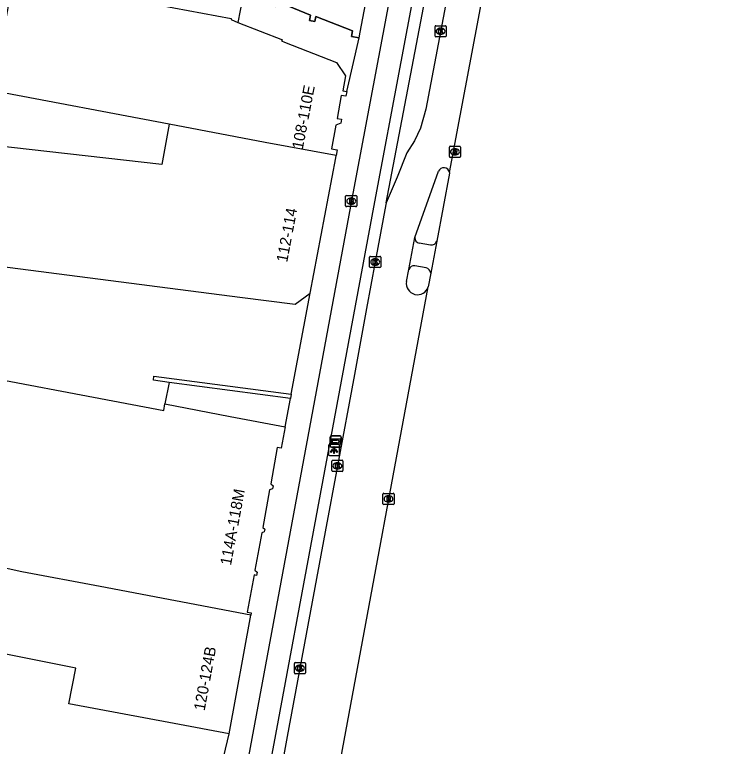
# Model space of a CAD drawing. Extents: x 161402 to 161933, y 381650 to 382313.
# Drawn here: x 161827.2 to 161890, y 381730.8 to 381796.3 of the extents above; entities that cross this region are included whole.
import ezdxf

# ---------------------------------------------------------------- set-up
doc = ezdxf.new("R2010")
doc.units = 0
for name, color, linetype in [('IMGEO_Brandkraan', 7, 'Continuous'), ('IMGEO_Fietspad_gesloten', 7, 'Continuous'), ('IMGEO_Kolk', 7, 'Continuous'), ('IMGEO_Lichtpunt', 7, 'Continuous'), ('IMGEO_OVBaan_gesloten', 7, 'Continuous'), ('IMGEO_Pand', 7, 'Continuous'), ('IMGEO_Pand_nummerreeks', 7, 'Continuous'), ('IMGEO_Pand_overbouw', 7, 'Continuous'), ('IMGEO_Parkeervlak_open', 7, 'Continuous'), ('IMGEO_Rijbaan_lokaal_gesloten', 7, 'Continuous'), ('IMGEO_Rioolput', 7, 'Continuous'), ('IMGEO_Voetpad_open', 7, 'Continuous'), ('IMGEO_Wegwijzer', 7, 'Continuous')]:
    doc.layers.add(name, color=color, linetype=linetype)

msp = doc.modelspace()

# ---------------------------------------------------------------- linework, layer by layer
at = {"layer": 'IMGEO_Brandkraan'}
for p, q in [((161856.902, 381779.209), (161856.902, 381780.061)), ((161856.977, 381780.135), (161857.829, 381780.135)), ((161857.903, 381780.061), (161857.903, 381779.209)), ((161857.413, 381779.355), (161857.388, 381779.355)), ((161857.39, 381779.915), (161857.415, 381779.915)), ((161857.829, 381779.135), (161856.977, 381779.135))]:
    msp.add_line(p, q, dxfattribs=at)
for points in [[(161856.902, 381779.209), (161856.902, 381780.061)], [(161856.977, 381780.135), (161857.829, 381780.135)], [(161857.903, 381780.061), (161857.903, 381779.209)], [(161857.25, 381779.835), (161857.25, 381779.435), (161857.463, 381779.435)], [(161857.481, 381779.835), (161857.25, 381779.835)], [(161857.429, 381779.754), (161857.375, 381779.754), (161857.375, 381779.678)], [(161857.375, 381779.678), (161857.428, 381779.678)], [(161857.437, 381779.602), (161857.375, 381779.602), (161857.375, 381779.521)], [(161857.375, 381779.521), (161857.437, 381779.521)], [(161857.829, 381779.135), (161856.977, 381779.135)]]:
    msp.add_lwpolyline(points, dxfattribs=at)
for centre, radius, start, end in [((161856.979, 381780.059), 0.0765, 91.55205, 178.44795), ((161856.979, 381780.059), 0.0765, 91.55205, 178.44795), ((161857.827, 381780.059), 0.0765, 1.55205, 88.44795), ((161857.827, 381780.059), 0.0765, 1.55205, 88.44795), ((161857.43, 381779.716), 0.0379, 267.82845, 90.93552), ((161857.438, 381779.561), 0.0404, 269.87594, 90.50774), ((161857.469, 381779.686), 0.251, 268.66757, 293.53466), ((161857.485, 381779.69), 0.145, 59.4692, 91.53667), ((161857.51, 381779.737), 0.0922, 285.51372, 58.15012), ((161857.515, 381779.545), 0.105, 301.31148, 78.98903), ((161856.979, 381779.211), 0.0765, 181.55205, 268.44795), ((161856.979, 381779.211), 0.0765, 181.55205, 268.44795), ((161857.827, 381779.211), 0.0765, 271.55205, 358.44795), ((161857.827, 381779.211), 0.0765, 271.55205, 358.44795)]:
    msp.add_arc(centre, radius, start, end, dxfattribs=at)
for centre, major_axis, ratio, start_param, end_param in [((161857.389, 381779.635), (-0.387, 0.002), 0.722429, 4.712389, 7.853982), ((161857.414, 381779.635), (-0.39, 0.002), 0.717154, 1.570796, 4.712389)]:
    msp.add_ellipse(centre, major_axis=major_axis, ratio=ratio, start_param=start_param, end_param=end_param, dxfattribs=at)
at = {"layer": 'IMGEO_Fietspad_gesloten'}
for points in [[(161886.669, 381935.154), (161880.56, 381902.497), (161879.486, 381896.758), (161857.65, 381780.798), (161851.928, 381750), (161842.232, 381697.819)], [(161844.249, 381697.445), (161849.541, 381725.922), (161850.643, 381731.85), (161854.016, 381750), (161859.509, 381779.56), (161864.254, 381804.698)]]:
    msp.add_lwpolyline(points, dxfattribs=at)
at = {"layer": 'IMGEO_Kolk'}
for p, q in [((161864.914, 381794.422), (161864.914, 381795.274)), ((161864.989, 381795.348), (161865.841, 381795.348)), ((161865.402, 381795.128), (161865.427, 381795.128)), ((161865.915, 381795.274), (161865.915, 381794.422)), ((161865.425, 381794.568), (161865.4, 381794.568)), ((161865.841, 381794.348), (161864.989, 381794.348)), ((161859.052, 381773.752), (161859.052, 381774.604)), ((161859.127, 381774.678), (161859.979, 381774.678)), ((161859.54, 381774.458), (161859.565, 381774.458)), ((161860.053, 381774.604), (161860.053, 381773.752)), ((161859.979, 381773.678), (161859.127, 381773.678)), ((161859.563, 381773.898), (161859.538, 381773.898)), ((161855.736, 381756.411), (161856.588, 381756.411)), ((161855.661, 381755.485), (161855.661, 381756.337)), ((161856.149, 381756.191), (161856.174, 381756.191)), ((161856.662, 381756.337), (161856.662, 381755.485)), ((161856.588, 381755.411), (161855.736, 381755.411)), ((161856.172, 381755.631), (161856.147, 381755.631)), ((161852.304, 381737.36), (161852.304, 381738.212)), ((161852.379, 381738.286), (161853.231, 381738.286)), ((161852.792, 381738.066), (161852.817, 381738.066)), ((161853.305, 381738.212), (161853.305, 381737.36)), ((161852.815, 381737.506), (161852.79, 381737.506)), ((161853.231, 381737.286), (161852.379, 381737.286))]:
    msp.add_line(p, q, dxfattribs=at)
for points in [[(161864.914, 381794.422), (161864.914, 381795.274)], [(161864.989, 381795.348), (161865.841, 381795.348)], [(161865.235, 381795.048), (161865.358, 381795.048), (161865.358, 381794.897), (161865.488, 381795.048), (161865.652, 381795.048), (161865.506, 381794.897), (161865.659, 381794.648), (161865.507, 381794.648), (161865.422, 381794.812), (161865.358, 381794.745), (161865.358, 381794.648), (161865.235, 381794.648), (161865.235, 381795.048)], [(161865.915, 381795.274), (161865.915, 381794.422)], [(161865.841, 381794.348), (161864.989, 381794.348)], [(161859.052, 381773.752), (161859.052, 381774.604)], [(161859.127, 381774.678), (161859.979, 381774.678)], [(161859.373, 381774.378), (161859.496, 381774.378), (161859.496, 381774.227), (161859.626, 381774.378), (161859.79, 381774.378), (161859.644, 381774.227), (161859.797, 381773.978), (161859.645, 381773.978), (161859.56, 381774.142), (161859.496, 381774.075), (161859.496, 381773.978), (161859.373, 381773.978), (161859.373, 381774.378)], [(161860.053, 381774.604), (161860.053, 381773.752)], [(161859.979, 381773.678), (161859.127, 381773.678)], [(161855.736, 381756.411), (161856.588, 381756.411)], [(161855.661, 381755.485), (161855.661, 381756.337)], [(161855.982, 381756.111), (161856.105, 381756.111), (161856.105, 381755.96), (161856.235, 381756.111), (161856.399, 381756.111), (161856.253, 381755.96), (161856.406, 381755.711), (161856.254, 381755.711), (161856.169, 381755.875), (161856.105, 381755.808), (161856.105, 381755.711), (161855.982, 381755.711), (161855.982, 381756.111)], [(161856.662, 381756.337), (161856.662, 381755.485)], [(161856.588, 381755.411), (161855.736, 381755.411)], [(161852.304, 381737.36), (161852.304, 381738.212)], [(161852.379, 381738.286), (161853.231, 381738.286)], [(161853.305, 381738.212), (161853.305, 381737.36)], [(161852.625, 381737.986), (161852.748, 381737.986), (161852.748, 381737.835), (161852.878, 381737.986), (161853.042, 381737.986), (161852.896, 381737.835), (161853.049, 381737.586), (161852.897, 381737.586), (161852.812, 381737.75), (161852.748, 381737.683), (161852.748, 381737.586), (161852.625, 381737.586), (161852.625, 381737.986)], [(161853.231, 381737.286), (161852.379, 381737.286)]]:
    msp.add_lwpolyline(points, dxfattribs=at)
for centre, start, end in [((161864.991, 381795.272), 91.55205, 178.44795), ((161864.991, 381795.272), 91.55205, 178.44795), ((161865.839, 381795.272), 1.55205, 88.44795), ((161865.839, 381795.272), 1.55205, 88.44795), ((161864.991, 381794.424), 181.55205, 268.44795), ((161864.991, 381794.424), 181.55205, 268.44795), ((161865.839, 381794.424), 271.55205, 358.44795), ((161865.839, 381794.424), 271.55205, 358.44795), ((161859.129, 381774.602), 91.55205, 178.44795), ((161859.129, 381774.602), 91.55205, 178.44795), ((161859.977, 381774.602), 1.55205, 88.44795), ((161859.977, 381774.602), 1.55205, 88.44795), ((161859.129, 381773.754), 181.55205, 268.44795), ((161859.129, 381773.754), 181.55205, 268.44795), ((161859.977, 381773.754), 271.55205, 358.44795), ((161859.977, 381773.754), 271.55205, 358.44795), ((161855.738, 381756.335), 91.55205, 178.44795), ((161855.738, 381756.335), 91.55205, 178.44795), ((161856.586, 381756.335), 1.55205, 88.44795), ((161856.586, 381756.335), 1.55205, 88.44795), ((161855.738, 381755.487), 181.55205, 268.44795), ((161855.738, 381755.487), 181.55205, 268.44795), ((161856.586, 381755.487), 271.55205, 358.44795), ((161856.586, 381755.487), 271.55205, 358.44795), ((161852.381, 381738.21), 91.55205, 178.44795), ((161852.381, 381738.21), 91.55205, 178.44795), ((161853.229, 381738.21), 1.55205, 88.44795), ((161853.229, 381738.21), 1.55205, 88.44795), ((161852.381, 381737.362), 181.55205, 268.44795), ((161852.381, 381737.362), 181.55205, 268.44795), ((161853.229, 381737.362), 271.55205, 358.44795), ((161853.229, 381737.362), 271.55205, 358.44795)]:
    msp.add_arc(centre, 0.0765, start, end, dxfattribs=at)
for centre, major_axis, ratio, start_param, end_param in [((161865.401, 381794.848), (-0.387, 0.002), 0.722429, 4.712389, 7.853982), ((161865.426, 381794.848), (-0.39, 0.002), 0.717154, 1.570796, 4.712389), ((161859.539, 381774.178), (-0.387, 0.002), 0.722429, 4.712389, 7.853982), ((161859.564, 381774.178), (-0.39, 0.002), 0.717154, 1.570796, 4.712389), ((161856.148, 381755.911), (-0.387, 0.002), 0.722429, 4.712389, 7.853982), ((161856.173, 381755.911), (-0.39, 0.002), 0.717154, 1.570796, 4.712389), ((161852.791, 381737.786), (-0.387, 0.002), 0.722429, 4.712389, 7.853982), ((161852.816, 381737.786), (-0.39, 0.002), 0.717154, 1.570796, 4.712389)]:
    msp.add_ellipse(centre, major_axis=major_axis, ratio=ratio, start_param=start_param, end_param=end_param, dxfattribs=at)
at = {"layer": 'IMGEO_Lichtpunt'}
for p, q in [((161855.356, 381757.739), (161855.356, 381756.932)), ((161855.356, 381757.739), (161855.356, 381756.932)), ((161856.258, 381757.834), (161855.45, 381757.834)), ((161856.258, 381757.834), (161855.45, 381757.834)), ((161856.352, 381756.932), (161856.352, 381757.739)), ((161856.352, 381756.932), (161856.352, 381757.739)), ((161855.45, 381756.838), (161856.258, 381756.838)), ((161855.45, 381756.838), (161856.258, 381756.838))]:
    msp.add_line(p, q, dxfattribs=at)
for points in [[(161855.73, 381757.403), (161855.769, 381757.375), (161855.581, 381757.113), (161855.543, 381757.14), (161855.73, 381757.403)], [(161855.832, 381757.355), (161855.879, 381757.355), (161855.879, 381757.033), (161855.832, 381757.033), (161855.832, 381757.355)], [(161855.942, 381757.375), (161855.98, 381757.402), (161856.167, 381757.14), (161856.128, 381757.112), (161855.942, 381757.375)]]:
    msp.add_lwpolyline(points, dxfattribs=at)
msp.add_circle((161855.855, 381757.537), 0.0994, dxfattribs=at)
for centre, start, end in [((161855.45, 381757.739), 90, 180), ((161855.45, 381757.739), 90, 180), ((161856.258, 381757.739), 0, 90), ((161856.258, 381757.739), 0, 90), ((161855.45, 381756.932), 180, 270), ((161855.45, 381756.932), 180, 270), ((161856.258, 381756.932), 270, 0), ((161856.258, 381756.932), 270, 360)]:
    msp.add_arc(centre, 0.0946, start, end, dxfattribs=at)
at = {"layer": 'IMGEO_OVBaan_gesloten'}
for points in [[(161866.208, 381782.197), (161889.963, 381908.334)], [(161866.208, 381782.197), (161866.199, 381782.149), (161865.069, 381776.053)], [(161865.069, 381776.053), (161864.537, 381773.18)], [(161864.537, 381773.18), (161864.311, 381771.961)], [(161856.328, 381728.885), (161864.311, 381771.961)]]:
    msp.add_lwpolyline(points, dxfattribs=at)
at = {"layer": 'IMGEO_Pand'}
for points in [[(161858.115, 381794.262), (161858.21, 381794.775), (161860.511, 381806.869)], [(161834.057, 381805.821), (161840.962, 381801.911), (161847.86, 381798.902), (161849.682, 381798.222), (161849.663, 381797.923), (161850.239, 381797.804), (161850.117, 381797.158), (161850.627, 381797.062), (161850.716, 381797.533), (161853.746, 381796.3), (161853.653, 381795.807), (161854.154, 381795.713), (161854.239, 381796.167), (161857.521, 381794.895), (161857.427, 381794.392), (161858.115, 381794.262)], [(161841.091, 381786.52), (161825.253, 381789.517), (161827.976, 381804.229), (161832.124, 381803.461), (161840.482, 381798.624), (161840.218, 381797.195), (161846.644, 381796.006), (161846.624, 381795.895), (161847.248, 381795.649), (161851.239, 381794.077), (161851.163, 381793.987), (161851.433, 381793.88), (161856.08, 381792.037), (161856.9, 381790.844), (161856.653, 381789.512), (161857.009, 381789.446)], [(161857.009, 381789.446), (161856.93, 381789.024), (161856.511, 381789.101), (161856.131, 381787.047), (161856.545, 381786.97), (161856.477, 381786.601), (161856.03, 381786.443), (161855.635, 381784.312), (161856.14, 381784.219), (161856.045, 381783.706)], [(161841.091, 381786.52), (161840.426, 381782.925), (161818.468, 381785.39), (161817.2, 381785.532), (161816.76, 381785.582), (161815.284, 381775.177), (161817.528, 381774.888), (161822.163, 381774.29), (161847.423, 381771.033), (161852.381, 381770.396), (161853.707, 381771.374)], [(161856.045, 381783.706), (161849.676, 381784.895), (161841.091, 381786.52)], [(161853.707, 381771.374), (161856.009, 381783.513), (161856.045, 381783.706)], [(161809.949, 381766.688), (161819.44, 381764.889), (161840.589, 381760.879), (161840.698, 381761.458), (161846.555, 381760.347), (161851.467, 381759.416)], [(161851.943, 381761.958), (161841.065, 381763.395), (161839.66, 381763.58), (161839.71, 381763.956), (161852.013, 381762.331)], [(161852.013, 381762.331), (161851.943, 381761.958)], [(161851.467, 381759.416), (161851.119, 381757.504), (161850.777, 381757.569), (161850.181, 381754.306), (161850.4, 381754.115), (161850.348, 381753.845), (161850.08, 381753.751), (161849.468, 381750.399), (161849.655, 381750.236), (161849.61, 381750), (161849.381, 381749.923), (161848.769, 381746.569), (161848.973, 381746.394), (161848.917, 381746.094), (161848.69, 381746.136), (161848.083, 381742.809), (161848.429, 381742.746), (161848.392, 381742.544)], [(161848.392, 381742.544), (161834.903, 381745.106), (161827.854, 381746.416), (161811.485, 381750), (161806.895, 381751.005)], [(161846.453, 381731.901), (161841.538, 381732.82), (161832.077, 381734.588), (161832.719, 381737.797), (161818.513, 381740.64), (161817.529, 381735.723), (161804.849, 381738.517), (161806.502, 381746.774), (161806.126, 381746.844)], [(161846.453, 381731.901), (161848.392, 381742.544)]]:
    msp.add_lwpolyline(points, dxfattribs=at)
at = {"layer": 'IMGEO_Pand_overbouw'}
for points in [[(161857.009, 381789.446), (161858.115, 381794.262), (161857.427, 381794.392), (161857.521, 381794.895), (161854.239, 381796.167), (161854.154, 381795.713), (161853.653, 381795.807), (161853.746, 381796.3), (161850.716, 381797.533), (161850.627, 381797.062), (161850.117, 381797.158), (161850.239, 381797.804), (161849.663, 381797.923), (161849.682, 381798.222), (161847.86, 381798.902), (161847.248, 381795.649), (161851.239, 381794.077), (161851.163, 381793.987), (161851.433, 381793.88), (161856.08, 381792.037), (161856.9, 381790.844), (161856.653, 381789.512)], [(161851.943, 381761.958), (161841.065, 381763.395), (161840.698, 381761.458), (161846.555, 381760.347), (161851.467, 381759.416)]]:
    msp.add_lwpolyline(points, close=True, dxfattribs=at)
at = {"layer": 'IMGEO_Parkeervlak_open'}
msp.add_lwpolyline([(161860.529, 381779.475), (161865.316, 381804.498)], dxfattribs=at)
at = {"layer": 'IMGEO_Rijbaan_lokaal_gesloten'}
for points in [[(161884.15, 381893.504), (161864.093, 381787.863), (161863.613, 381786.178), (161863.081, 381785.029), (161862.376, 381783.945), (161861.521, 381781.789), (161860.529, 381779.475)], [(161863.119, 381776.384), (161865.223, 381782.305)], [(161860.529, 381779.475), (161860.503, 381779.34), (161859.554, 381774.178), (161858.781, 381770.01), (161857.682, 381764.091), (161856.164, 381755.911), (161855.069, 381750), (161851.669, 381731.66), (161850.569, 381725.731), (161845.879, 381700.449), (161845.656, 381699.227), (161845.077, 381696.29), (161841.891, 381681.821), (161841.621, 381680.659), (161841.162, 381678.679), (161840.43, 381675.643), (161840.392, 381675.483)], [(161862.572, 381773.513), (161863.119, 381776.384)], [(161862.351, 381772.437), (161862.572, 381773.513)]]:
    msp.add_lwpolyline(points, dxfattribs=at)
for centre, radius, start, end in [((161865.701, 381782.116), 0.514, 9.0565, 158.42913), ((161863.346, 381772.259), 1.01, 169.85697, 342.84219)]:
    msp.add_arc(centre, radius, start, end, dxfattribs=at)
at = {"layer": 'IMGEO_Rioolput'}
for p, q in [((161866.201, 381783.62), (161866.201, 381784.472)), ((161866.276, 381784.546), (161867.128, 381784.546)), ((161866.689, 381784.326), (161866.714, 381784.326)), ((161867.202, 381784.472), (161867.202, 381783.62)), ((161867.128, 381783.546), (161866.276, 381783.546)), ((161866.712, 381783.766), (161866.687, 381783.766)), ((161860.244, 381752.526), (161860.244, 381753.378)), ((161860.319, 381753.452), (161861.171, 381753.452)), ((161860.732, 381753.232), (161860.757, 381753.232)), ((161861.245, 381753.378), (161861.245, 381752.526)), ((161861.171, 381752.452), (161860.319, 381752.452)), ((161860.755, 381752.672), (161860.73, 381752.672))]:
    msp.add_line(p, q, dxfattribs=at)
for points in [[(161866.201, 381783.62), (161866.201, 381784.472)], [(161866.276, 381784.546), (161867.128, 381784.546)], [(161866.79, 381784.244), (161866.538, 381784.246), (161866.538, 381783.846)], [(161866.538, 381783.846), (161866.662, 381783.846), (161866.662, 381784.008), (161866.673, 381784.008)], [(161866.716, 381784.165), (161866.662, 381784.165), (161866.662, 381784.084)], [(161866.662, 381784.084), (161866.714, 381784.084)], [(161866.72, 381783.979), (161866.791, 381783.846), (161866.931, 381783.846), (161866.866, 381783.972)], [(161867.202, 381784.472), (161867.202, 381783.62)], [(161867.128, 381783.546), (161866.276, 381783.546)], [(161860.244, 381752.526), (161860.244, 381753.378)], [(161860.319, 381753.452), (161861.171, 381753.452)], [(161860.833, 381753.15), (161860.581, 381753.152), (161860.581, 381752.752)], [(161861.245, 381753.378), (161861.245, 381752.526)], [(161861.171, 381752.452), (161860.319, 381752.452)], [(161860.581, 381752.752), (161860.705, 381752.752), (161860.705, 381752.914), (161860.716, 381752.914)], [(161860.759, 381753.071), (161860.705, 381753.071), (161860.705, 381752.99)], [(161860.705, 381752.99), (161860.757, 381752.99)], [(161860.763, 381752.885), (161860.834, 381752.752), (161860.974, 381752.752), (161860.909, 381752.878)]]:
    msp.add_lwpolyline(points, dxfattribs=at)
for centre, radius, start, end in [((161866.278, 381784.47), 0.0765, 91.55205, 178.44795), ((161866.278, 381784.47), 0.0765, 91.55205, 178.44795), ((161866.672, 381783.955), 0.0533, 26.02933, 88.69889), ((161866.698, 381784.273), 0.19, 274.7715, 282.96867), ((161866.722, 381784.069), 0.0964, 77.00612, 93.18647), ((161866.736, 381784.126), 0.0378, 276.66336, 79.67722), ((161866.789, 381784.134), 0.109, 350.36119, 89.41601), ((161866.787, 381784.134), 0.112, 277.58423, 350.98172), ((161866.771, 381783.919), 0.108, 29.51342, 73.79051), ((161867.126, 381784.47), 0.0765, 1.55205, 88.44795), ((161867.126, 381784.47), 0.0765, 1.55205, 88.44795), ((161866.278, 381783.622), 0.0765, 181.55205, 268.44795), ((161866.278, 381783.622), 0.0765, 181.55205, 268.44795), ((161867.126, 381783.622), 0.0765, 271.55205, 358.44795), ((161867.126, 381783.622), 0.0765, 271.55205, 358.44795), ((161860.321, 381753.376), 0.0765, 91.55205, 178.44795), ((161860.321, 381753.376), 0.0765, 91.55205, 178.44795), ((161860.832, 381753.04), 0.109, 350.36119, 89.41601), ((161861.169, 381753.376), 0.0765, 1.55205, 88.44795), ((161861.169, 381753.376), 0.0765, 1.55205, 88.44795), ((161860.321, 381752.528), 0.0765, 181.55205, 268.44795), ((161860.321, 381752.528), 0.0765, 181.55205, 268.44795), ((161860.715, 381752.861), 0.0533, 26.02933, 88.69889), ((161860.741, 381753.179), 0.19, 274.7715, 282.96867), ((161860.765, 381752.975), 0.0964, 77.00612, 93.18647), ((161860.779, 381753.032), 0.0378, 276.66336, 79.67722), ((161860.83, 381753.04), 0.112, 277.58423, 350.98172), ((161860.814, 381752.825), 0.108, 29.51342, 73.79051), ((161861.169, 381752.528), 0.0765, 271.55205, 358.44795), ((161861.169, 381752.528), 0.0765, 271.55205, 358.44795)]:
    msp.add_arc(centre, radius, start, end, dxfattribs=at)
for centre, major_axis, ratio, start_param, end_param in [((161866.688, 381784.046), (-0.387, 0.002), 0.722429, 4.712389, 7.853982), ((161866.713, 381784.046), (-0.39, 0.002), 0.717154, 1.570796, 4.712389), ((161860.731, 381752.952), (-0.387, 0.002), 0.722429, 4.712389, 7.853982), ((161860.756, 381752.952), (-0.39, 0.002), 0.717154, 1.570796, 4.712389)]:
    msp.add_ellipse(centre, major_axis=major_axis, ratio=ratio, start_param=start_param, end_param=end_param, dxfattribs=at)
at = {"layer": 'IMGEO_Voetpad_open'}
for points in [[(161857.009, 381789.446), (161858.115, 381794.262)], [(161863.506, 381775.88), (161864.518, 381775.728)], [(161864.121, 381773.647), (161863.115, 381773.82)], [(161852.013, 381762.331), (161853.707, 381771.374)], [(161851.467, 381759.416), (161851.943, 381761.958)], [(161845.322, 381727.164), (161846.453, 381731.901)]]:
    msp.add_lwpolyline(points, dxfattribs=at)
for centre, radius, start, end in [((161863.571, 381776.33), 0.455, 173.1959, 261.84233), ((161864.611, 381776.199), 0.48, 258.78728, 342.28005), ((161863.002, 381773.386), 0.449, 75.46093, 163.50476), ((161863.998, 381773.119), 0.542, 6.47187, 76.91693)]:
    msp.add_arc(centre, radius, start, end, dxfattribs=at)
at = {"layer": 'IMGEO_Wegwijzer'}
for p, q in [((161855.523, 381757.698), (161855.523, 381758.498)), ((161855.523, 381758.498), (161855.523, 381757.698)), ((161855.623, 381758.598), (161856.413, 381758.598)), ((161856.413, 381758.598), (161855.623, 381758.598)), ((161856.513, 381758.498), (161856.513, 381757.698)), ((161856.513, 381757.698), (161856.513, 381758.498)), ((161856.413, 381757.598), (161855.623, 381757.598)), ((161855.623, 381757.598), (161856.413, 381757.598))]:
    msp.add_line(p, q, dxfattribs=at)
for points in [[(161855.624, 381758.33), (161856.412, 381758.33), (161856.412, 381757.866), (161855.624, 381757.866), (161855.624, 381758.33)], [(161855.689, 381758.182), (161855.689, 381758.098), (161855.689, 381758.014), (161856.1, 381758.014), (161856.1, 381757.931), (161856.347, 381758.098), (161856.1, 381758.265), (161856.1, 381758.182), (161855.689, 381758.182)]]:
    msp.add_lwpolyline(points, dxfattribs=at)
for centre, start, end in [((161855.623, 381758.498), 90, 180), ((161855.623, 381758.498), 90, 180), ((161856.413, 381758.498), 0, 90), ((161856.413, 381758.498), 360, 90), ((161855.623, 381757.698), 180, 270), ((161855.623, 381757.698), 180, 270), ((161856.413, 381757.698), 270, 0), ((161856.413, 381757.698), 270, 0)]:
    msp.add_arc(centre, 0.1, start, end, dxfattribs=at)

# ---------------------------------------------------------------- texts
at = {"layer": 'IMGEO_Pand_nummerreeks'}
for s, rotation, p in [('108-110E', 79.11401, (161853.053, 381784.218)), ('112-114', 79.26298, (161851.657, 381774.094)), ('114A-118M', 79.49216, (161846.618, 381746.946)), ('120-124B', 79.67551, (161844.26, 381733.922))]:
    msp.add_text(s, height=1, rotation=rotation, dxfattribs=at).set_placement(p)

doc.saveas('drawing.dxf')
